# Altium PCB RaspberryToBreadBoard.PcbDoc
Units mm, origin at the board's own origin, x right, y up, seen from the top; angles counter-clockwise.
Board outline 21.59 x 43.18 mm, 2 copper layers (Top Layer, Bottom Layer); 3 components, 20 nets, 52 pads, 26 vias.
Unrouted connection lines stored in the file: 2.
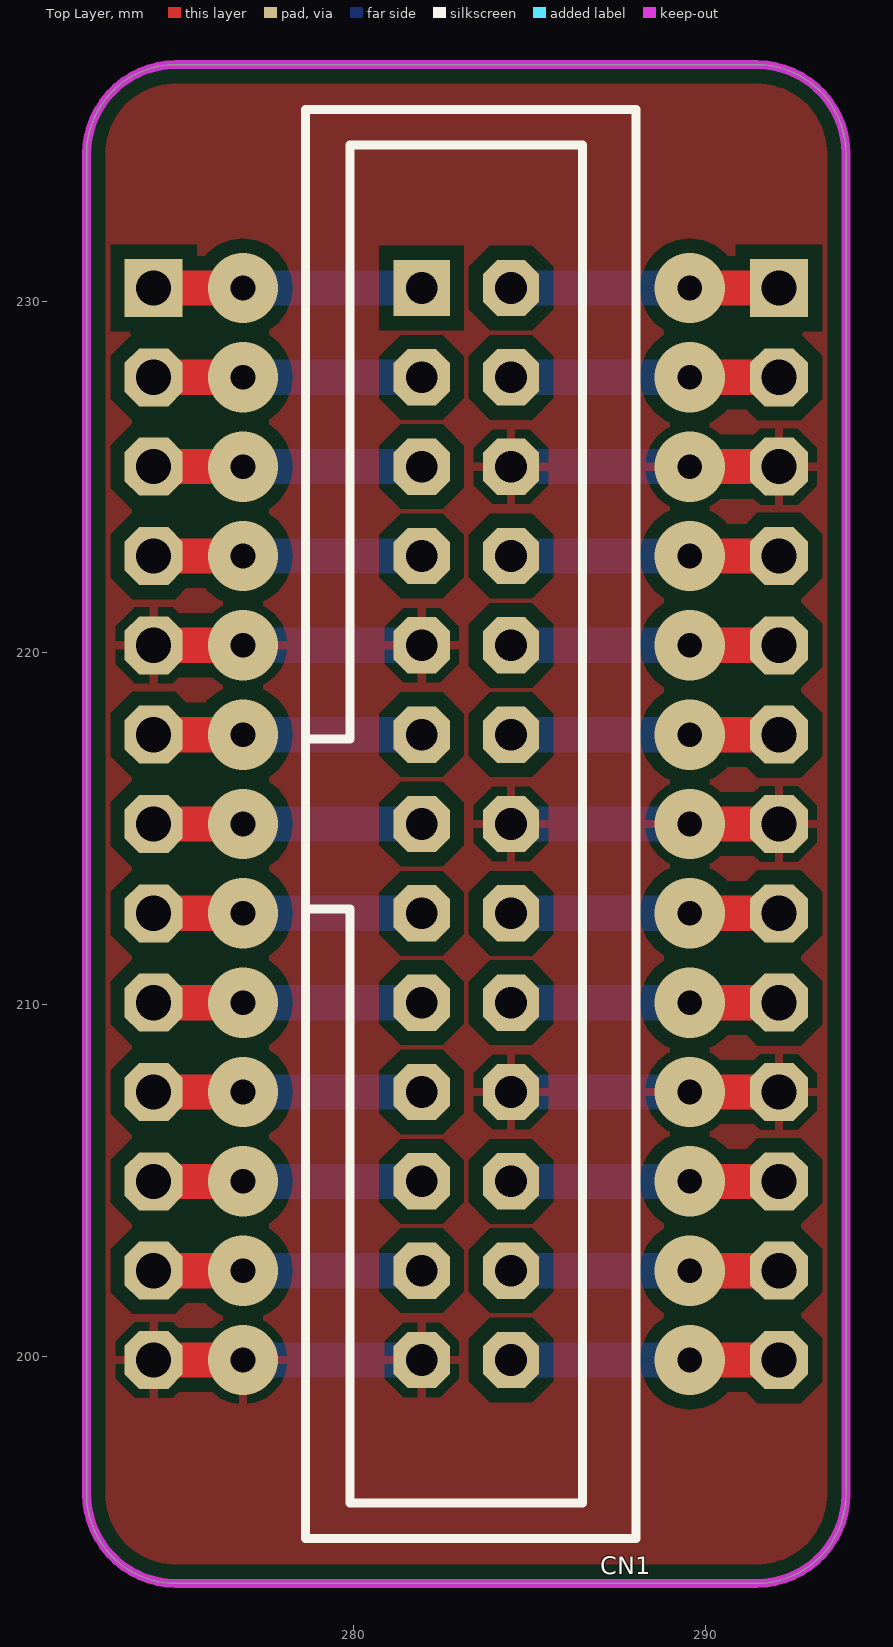
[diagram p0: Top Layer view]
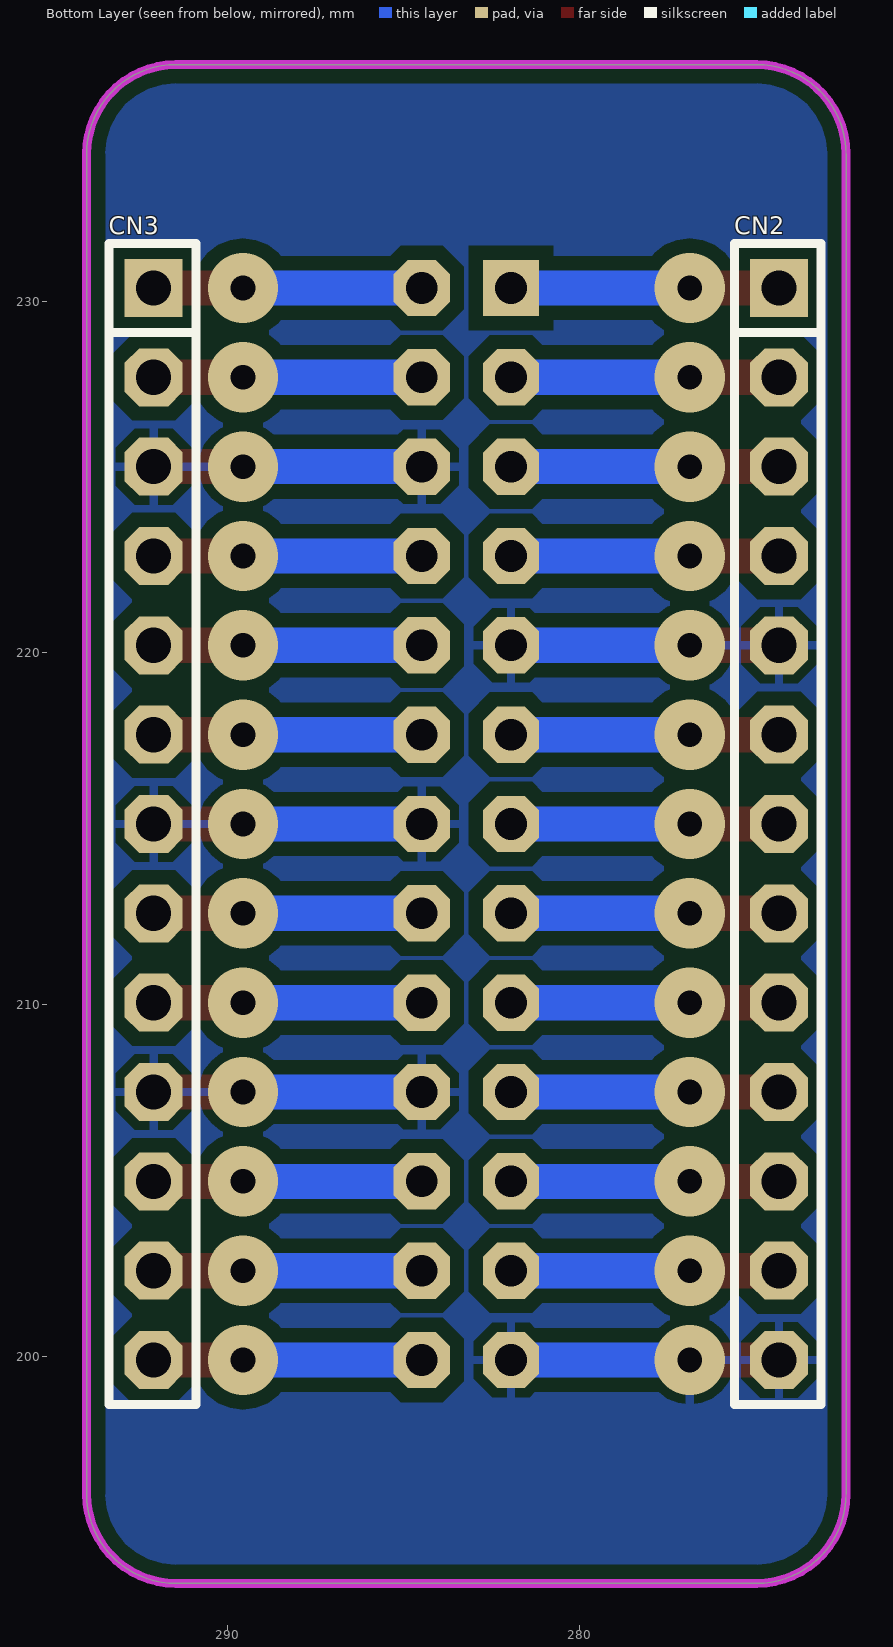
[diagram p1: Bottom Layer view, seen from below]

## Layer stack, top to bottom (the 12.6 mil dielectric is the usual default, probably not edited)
Top Layer: signal copper 0.0356
Dielectric: dielectric 0.32, FR-4, Dk 4.8
Bottom Layer: signal copper 0.0356

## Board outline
272.415,196.088 ccw(c274.955,196.088) 274.955,193.548 291.465,193.548 ccw(c291.465,196.088) 294.005,196.088 294.005,234.188 ccw(c291.465,234.188) 291.465,236.728 274.955,236.728 ccw(c274.955,234.188) 272.415,234.188

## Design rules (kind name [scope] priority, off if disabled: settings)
Clearance [All] p1: gap=0.4
PolygonConnect [All] p1: connectstyle=Relief reliefconductorwidth=0.254 reliefentries=4 polygonreliefangle="90 Angle" airgapwidth=0.254
RoomDefinition sch [InComponentClass('sch')] p1: confinementstyle=ConfineIn formatcopy=TRUE lockcomponents=FALSE outline 262.89,183.896 304.292,183.896 304.292,244.348 262.89,244.348
RoutingVias [All] p1: holewidth=0.7 width=2 viastyle="Through Hole" minholewidth=0.7 minwidth=2 maxholewidth=0.7 maxwidth=2
SilkToSolderMaskClearance SilkscreenOverComponentPads [IsPad] p1: minsilkscreentomaskgap=0.254 clearancetoexposedcopper=TRUE
SolderMaskExpansion [All] p1: expansion=0.102
Width [All] p1: maxlimit=1 minlimit=0.3 preferedwidth=0.5
27 further rules are at their usual default settings.

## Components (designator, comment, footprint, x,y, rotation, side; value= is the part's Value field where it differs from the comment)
CN1 "IDC Connector" IDC26 281.94,230.378 r270 top
CN2 "CN_13x1" GP_13x1 274.32,230.378 r270 bottom
CN3 "CN_13x1" GP_13x1 292.1,230.378 r270 bottom

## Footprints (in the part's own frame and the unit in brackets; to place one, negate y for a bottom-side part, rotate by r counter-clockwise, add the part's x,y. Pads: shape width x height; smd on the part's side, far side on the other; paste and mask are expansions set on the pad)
GP_13x1 [mil]
  rect 65x65 hole 39.37: 1(0,0)
  oct 65x65 hole 39.37: 2(100,0) 3(200,0) 4(300,0) 5(400,0) 6(500,0) 7(600,0) 8(700,0) 9(800,0) 10(900,0) 11(1000,0) 12(1100,0) 13(1200,0)
  silkscreen extent -50,-50 1250,47, body extent -50,-50 1250,50, height 330
IDC26 [mm] "2.54mm, 26 Pin IDC Male Connector"
  rect 1.6x1.6 hole 0.9: 1(0,0)
  oct 1.6x1.6 hole 0.9: 2(0,2.54) 3(2.54,0) 4(2.54,2.54) 5(5.08,0) 6(5.08,2.54) 7(7.62,0) 8(7.62,2.54) 9(10.16,0) 10(10.16,2.54) 11(12.7,0) 12(12.7,2.54) 13(15.24,0) 14(15.24,2.54) 15(17.78,0) 16(17.78,2.54) 17(20.32,0) 18(20.32,2.54) 19(22.86,0) 20(22.86,2.54) 21(25.4,0) 22(25.4,2.54) 23(27.94,0) 24(27.94,2.54) 25(30.48,0) 26(30.48,2.54)
  silkscreen extent -5.08,-3.3 35.56,6.1, body extent -5.08,-3.49 35.56,5.91, height 9.29

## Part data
CN1: library part CN_13x2

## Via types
v1: diameter 2, hole 0.7, Top Layer to Bottom Layer, 26 vias

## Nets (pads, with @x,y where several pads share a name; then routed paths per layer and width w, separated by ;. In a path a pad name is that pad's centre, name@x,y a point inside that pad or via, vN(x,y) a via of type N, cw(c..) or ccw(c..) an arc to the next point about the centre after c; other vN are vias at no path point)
3V3: CN1.1 CN1.17 CN2.1 CN2.9 | length 15.2
  Top Layer w1: CN2.9 v1(276.86,210.058) ; CN2.1 v1(276.86,230.378)
  Bottom Layer w1: v1(276.86,210.058) CN1.17 ; v1(276.86,230.378) CN1.1
5V: CN1.2 CN1.4 CN3.1 CN3.2 | length 15.2
  Top Layer w1: v1(289.56,227.838) CN3.2 ; v1(289.56,230.378) CN3.1
  Bottom Layer w1: CN1.4 v1(289.56,227.838) ; CN1.2 v1(289.56,230.378)
GND: CN1.6 CN1.9 CN1.14 CN1.20 CN1.25 CN2.5 CN2.13 CN3.3 CN3.7 CN3.10 | length 38.1
  Top Layer w1: CN2.13 v1(276.86,199.898) ; CN2.5 v1(276.86,220.218) ; v1(289.56,207.518) CN3.10 ; v1(289.56,215.138) CN3.7 ; v1(289.56,225.298) CN3.3
  Bottom Layer w1: v1(276.86,199.898) CN1.25 ; v1(276.86,220.218) CN1.9 ; CN1.20 v1(289.56,207.518) ; CN1.14 v1(289.56,215.138) ; CN1.6 v1(289.56,225.298)
GPIO2: CN1.3 CN2.2 | length 7.6
  Top Layer w1: CN2.2 v1(276.86,227.838)
  Bottom Layer w1: v1(276.86,227.838) CN1.3
GPIO3: CN1.5 CN2.3 | length 7.6
  Top Layer w1: CN2.3 v1(276.86,225.298)
  Bottom Layer w1: v1(276.86,225.298) CN1.5
GPIO4: CN1.7 CN2.4 | length 7.6
  Top Layer w1: CN2.4 v1(276.86,222.758)
  Bottom Layer w1: v1(276.86,222.758) CN1.7
GPIO7: CN1.26 CN3.13 | length 7.6
  Top Layer w1: v1(289.56,199.898) CN3.13
  Bottom Layer w1: CN1.26 v1(289.56,199.898)
GPIO8: CN1.24 CN3.12 | length 7.6
  Top Layer w1: v1(289.56,202.438) CN3.12
  Bottom Layer w1: CN1.24 v1(289.56,202.438)
GPIO9: CN1.21 CN2.11 | length 7.6
  Top Layer w1: CN2.11 v1(276.86,204.978)
  Bottom Layer w1: v1(276.86,204.978) CN1.21
GPIO10: CN1.19 CN2.10 | length 7.6
  Top Layer w1: CN2.10 v1(276.86,207.518)
  Bottom Layer w1: v1(276.86,207.518) CN1.19
GPIO11: CN1.23 CN2.12 | length 7.6
  Top Layer w1: CN2.12 v1(276.86,202.438)
  Bottom Layer w1: v1(276.86,202.438) CN1.23
GPIO14: CN1.8 CN3.4 | length 7.6
  Top Layer w1: v1(289.56,222.758) CN3.4
  Bottom Layer w1: CN1.8 v1(289.56,222.758)
GPIO15: CN1.10 CN3.5 | length 7.6
  Top Layer w1: v1(289.56,220.218) CN3.5
  Bottom Layer w1: CN1.10 v1(289.56,220.218)
GPIO17: CN1.11 CN2.6 | length 7.6
  Top Layer w1: CN2.6 v1(276.86,217.678)
  Bottom Layer w1: v1(276.86,217.678) CN1.11
GPIO18: CN1.12 CN3.6 | length 7.6
  Top Layer w1: v1(289.56,217.678) CN3.6
  Bottom Layer w1: CN1.12 v1(289.56,217.678)
GPIO22: CN1.15 CN2.8 | length 7.6
  Top Layer w1: CN2.8 v1(276.86,212.598)
  Bottom Layer w1: v1(276.86,212.598) CN1.15
GPIO23: CN1.16 CN3.8 | length 7.6
  Top Layer w1: v1(289.56,212.598) CN3.8
  Bottom Layer w1: CN1.16 v1(289.56,212.598)
GPIO24: CN1.18 CN3.9 | length 7.6
  Top Layer w1: v1(289.56,210.058) CN3.9
  Bottom Layer w1: CN1.18 v1(289.56,210.058)
GPIO25: CN1.22 CN3.11 | length 7.6
  Top Layer w1: v1(289.56,204.978) CN3.11
  Bottom Layer w1: CN1.22 v1(289.56,204.978)
GPIO27: CN1.13 CN2.7 | length 7.6
  Top Layer w1: CN2.7 v1(276.86,215.138)
  Bottom Layer w1: v1(276.86,215.138) CN1.13

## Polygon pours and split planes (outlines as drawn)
GND on Top Layer "Keep-Out Layer-No Net" (solid, pour order 4): 272.415,236.728 294.005,236.728 294.005,193.548 272.415,193.548
GND on Bottom Layer "Keep-Out Layer-No Net" (solid, pour order 3): 272.415,236.728 294.005,236.728 294.005,193.548 272.415,193.548

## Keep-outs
Keep-Out Layer:
  the board outline again, w0.254

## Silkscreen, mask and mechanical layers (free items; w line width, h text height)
Mechanical 16:
  lines w0.127: 133.772,156.561 138.852,156.561 ; 133.772,204.821 138.852,204.821 ; 133.772,253.081 138.852,253.081 ; 206.797,108.301 206.797,113.381 ; 206.797,296.261 206.797,301.341 ; 270.932,113.381 306.492,113.381 ; 279.822,108.301 279.822,113.381 ; 279.822,296.261 279.822,301.341 ; 300.879,113.406 300.904,113.381 ; 315.714,113.395 315.714,136.483 420.785,136.483 ; 315.74,128.965 420.759,128.965 ; 315.765,120.989 420.759,120.989 ; 334.695,113.395 334.695,120.989 ; 334.715,116.976 420.759,116.976 ; 352.847,296.261 352.847,301.341 ; 366.235,113.446 366.235,120.964 ; 395.165,120.989 395.165,136.483 ; 410.19,128.965 410.19,136.48 ; 420.792,156.561 425.872,156.561 ; 420.792,204.821 425.872,204.821 ; 420.792,253.081 425.872,253.081 ; 133.772,108.301 133.772,301.341 425.872,301.341 425.872,108.301 133.772,108.301 ; 138.852,113.381 420.792,113.381 420.792,138.654 420.792,296.261 138.852,296.261 138.852,113.381
  text "1" at 170.018,297.912 h1.78
  text "2" at 242.662,297.912 h1.78
  text "3" at 315.814,297.912 h1.78
  text "4" at 388.712,297.912 h1.78
  text "A" at 135.677,274.9 h1.78
  text "A" at 422.697,274.9 h1.78
  text "B" at 135.677,226.843 h1.78
  text "B" at 422.697,226.843 h1.78
  text "C" at 135.677,178.329 h1.78
  text "C" at 422.697,178.329 h1.78
  text "PROJECT NAME:" at 316.629,134.477 h1.14
  text "REVISION:" at 396.079,134.477 h1.14
  text "A4" at 413.54,131.405 h2.29
  text "RaspberryToBreadBoard" at 336.042,131.064 h2.54
  text "1.0.0" at 399.365,130.63 h1.78
  text "D" at 135.677,130.323 h1.78
  text "PROJECT NUMBER:" at 396.054,126.958 h1.14
  text "TITLE:" at 316.603,126.882 h1.14
  text "Raspberry To BreadBoard Converter" at 329.184,122.936 h2.16
  text "ONW-000" at 403.54,122.781 h1.78
  text "DATE:" at 316.73,118.78 h1.14
  text "JFK" at 384.498,118.296 h1.52
  text "1" at 345.917,118.221 h1.52
  text "DRAWN BY:" at 367.302,118.22 h1.52
  text "of" at 349.6,118.145 h1.52
  text "1" at 354.02,118.145 h1.52
  text "SHEET" at 336.138,118.119 h1.52
  text "12/04/2013" at 317.899,114.665 h1.52
  text "JFK" at 384.524,114.664 h1.52
  text "CHECKED BY:" at 367.277,114.537 h1.52
  text ".PCB_FILE_NAME_NO_PATH" at 336.037,114.512 h1.52
  text "1" at 170.018,109.952 h1.78
  text "2" at 242.662,109.952 h1.78

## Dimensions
274.32,199.898 to 292.1,199.898 on Mechanical 3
